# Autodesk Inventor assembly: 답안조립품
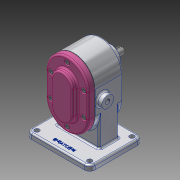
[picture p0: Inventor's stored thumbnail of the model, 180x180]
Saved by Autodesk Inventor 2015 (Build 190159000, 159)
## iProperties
Created: 2020-09
Part Number: 답안조립품
Document SubType Name: Assembly
Designer: Administrator
Author: Administrator
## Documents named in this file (11)
- C:\Users\Administrator.SC-201901281753\Desktop\700906v1030\답안조립품.iam
- C:\Users\Administrator.SC-201901281753\Desktop\700906v1030\본체.ipt
- C:\Users\Administrator.SC-201901281753\Desktop\700906v1030\메인축.ipt
- C:\Users\Administrator.SC-201901281753\Desktop\700906v1030\키 6 x 6 x 18.ipt
- C:\Users\Administrator.SC-201901281753\Desktop\700906v1030\스퍼기어.ipt
- C:\Users\Administrator.SC-201901281753\Desktop\700906v1030\베어링부시.ipt
- C:\Users\Administrator.SC-201901281753\Desktop\700906v1030\서브축.ipt
- C:\Users\Administrator.SC-201901281753\Desktop\700906v1030\개스킷.ipt
- C:\Users\Administrator.SC-201901281753\Desktop\700906v1030\커버.ipt
- C:\Users\Administrator.SC-201901281753\Desktop\700906v1030\오일 실 16 28 7.ipt
- C:\Users\Administrator.SC-201901281753\Desktop\700906v1030\볼트 M5.ipt
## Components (1 placed, 1 different names)
1. 개스킷:1
